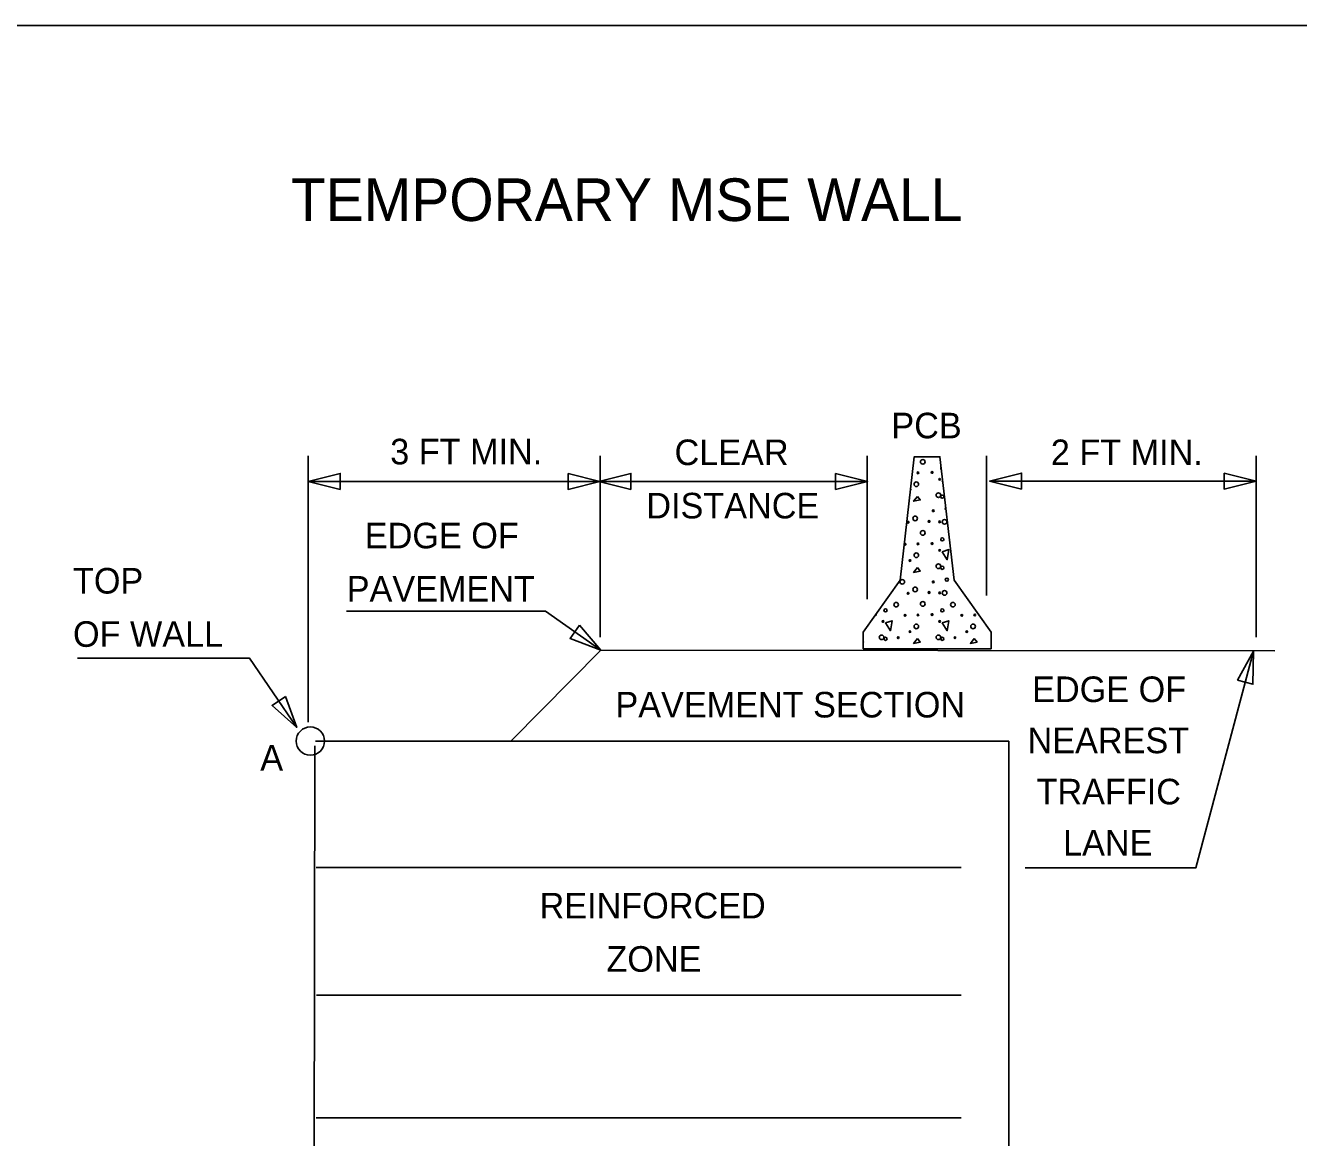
# Model space of a CAD drawing. Extents: x 2487012 to 2497594, y 369516 to 371986.
# Drawn here: x 2487358.3 to 2487671.9, y 370984.4 to 371258.3 of the extents above; entities that cross this region are included whole.
import ezdxf

# ---------------------------------------------------------------- set-up
doc = ezdxf.new("R2010")
doc.units = 0
for name, color, linetype in [('TC LABEL TEMP SHORING', 7, 'Continuous'), ('TC LABEL TEXT', 7, 'Continuous'), ('TC SHEET LAYOUT SHAPE', 7, 'Continuous')]:
    doc.layers.add(name, color=color, linetype=linetype)

msp = doc.modelspace()

# ---------------------------------------------------------------- linework, layer by layer
at = {"layer": 'TC LABEL TEMP SHORING'}
for p, q in [((2487427.93, 371086.68), (2487427.93, 371152.28)), ((2487499.91, 371107.65), (2487499.91, 371152.28)), ((2487565.64, 371117), (2487565.64, 371152.28)), ((2487595.06, 371117.94), (2487595.06, 371152.28)), ((2487661.45, 371107.65), (2487661.45, 371152.28)), ((2487584.22, 371146.19), (2487584.11, 371146.15)), ((2487584.11, 371146.15), (2487584.25, 371145.92)), ((2487600.51, 371082), (2487429.77, 371082)), ((2487600.51, 370878.76), (2487600.51, 371082)), ((2487429.59, 371080.9), (2487429.28, 370877.67)), ((2487429.94, 371050.89), (2487588.75, 371050.89)), ((2487429.98, 371019.52), (2487588.8, 371019.52)), ((2487429.94, 370989.28), (2487588.75, 370989.28))]:
    msp.add_line(p, q, dxfattribs=at)
for points in [[(2487564.64, 371104.8), (2487596.14, 371104.8), (2487596.14, 371108.85), (2487587.03, 371121.69), (2487583.55, 371152.05), (2487577.22, 371152.05), (2487573.74, 371121.69), (2487564.64, 371108.85)], [(2487578.01, 371142.31), (2487577.08, 371141.1), (2487578.72, 371141.42)], [(2487584.11, 371128.65), (2487585.35, 371126.72), (2487585.74, 371129.2)], [(2487578.01, 371124.81), (2487577.08, 371123.6), (2487578.72, 371123.92)], [(2487570.13, 371111.15), (2487571.37, 371109.22), (2487571.75, 371111.7)], [(2487584.11, 371111.15), (2487585.35, 371109.22), (2487585.74, 371111.7)], [(2487578.01, 371107.32), (2487577.08, 371106.1), (2487578.72, 371106.42)], [(2487591.99, 371107.32), (2487591.06, 371106.1), (2487592.7, 371106.42)]]:
    msp.add_lwpolyline(points, close=True, dxfattribs=at)
for points in [[(2487564.64, 371106.4), (2487564.74, 371106.42), (2487564.64, 371106.55)], [(2487478.05, 371082.22), (2487500.05, 371104.41), (2487666.03, 371104.31)]]:
    msp.add_lwpolyline(points, dxfattribs=at)
for centre, radius in [((2487579.33, 371150.82), 0.57), ((2487578.16, 371148.11), 0.209), ((2487581.63, 371148.2), 0.209), ((2487577.74, 371145.3), 0.57), ((2487583.5, 371146.51), 0.209), ((2487583.17, 371142.6), 0.57), ((2487584.13, 371142.23), 0.386), ((2487581.91, 371138.76), 0.209), ((2487575.72, 371135.95), 0.209), ((2487577.45, 371136.88), 0.57), ((2487580.88, 371136.14), 0.209), ((2487583.5, 371136.04), 0.209), ((2487584.69, 371136.04), 0.57), ((2487579.33, 371133.32), 0.57), ((2487584.13, 371131.73), 0.386), ((2487574.97, 371130.51), 0.209), ((2487577.74, 371127.8), 0.57), ((2487578.16, 371130.61), 0.209), ((2487581.63, 371130.7), 0.209), ((2487583.5, 371129.01), 0.209), ((2487576.19, 371126.51), 0.209), ((2487583.17, 371125.1), 0.57), ((2487584.13, 371124.73), 0.386), ((2487585.25, 371121.82), 0.386), ((2487574.27, 371121.26), 0.57), ((2487577.45, 371119.39), 0.57), ((2487580.88, 371118.64), 0.209), ((2487581.91, 371121.26), 0.209), ((2487583.5, 371118.54), 0.209), ((2487584.69, 371118.54), 0.57), ((2487572.77, 371115.64), 0.57), ((2487575.72, 371118.45), 0.209), ((2487579.33, 371115.82), 0.57), ((2487586.75, 371115.64), 0.57), ((2487570.15, 371114.23), 0.386), ((2487574.97, 371113.01), 0.209), ((2487578.16, 371113.11), 0.209), ((2487581.63, 371113.2), 0.209), ((2487584.13, 371114.23), 0.386), ((2487588.95, 371113.01), 0.209), ((2487592.14, 371113.11), 0.209), ((2487569.52, 371111.52), 0.209), ((2487577.74, 371110.3), 0.57), ((2487583.5, 371111.52), 0.209), ((2487591.72, 371110.3), 0.57), ((2487569.19, 371107.6), 0.57), ((2487570.15, 371107.23), 0.386), ((2487573.29, 371107.51), 0.209), ((2487576.19, 371109.01), 0.209), ((2487583.17, 371107.6), 0.57), ((2487584.13, 371107.23), 0.386), ((2487587.27, 371107.51), 0.209), ((2487590.17, 371109.01), 0.209)]:
    msp.add_circle(centre, radius, dxfattribs=at)
for centre, radius, start, end in [((2487584.13, 371149.23), 0.386, 137.1025, 235.9904), ((2487576.19, 371144.01), 0.209, 294.7417, 52.1654), ((2487585.25, 371139.32), 0.386, 134.7035, 238.3894), ((2487567.64, 371113.2), 0.209, 251.456, 37.8657)]:
    msp.add_arc(centre, radius, start, end, dxfattribs=at)
at = {"layer": 'TC LABEL TEXT'}
msp.add_line((2487595.79, 371146.09), (2487661.42, 371146.09), dxfattribs=at)
for points in [[(2487435.86, 371144.03), (2487427.98, 371146), (2487435.86, 371147.97)], [(2487435.86, 371144.03), (2487427.98, 371146), (2487435.86, 371147.97)], [(2487435.86, 371144.03), (2487427.98, 371146), (2487435.86, 371147.97)], [(2487435.86, 371144.03), (2487427.98, 371146), (2487435.86, 371147.97)], [(2487491.95, 371147.97), (2487499.83, 371146), (2487491.95, 371144.03)], [(2487491.95, 371147.97), (2487499.83, 371146), (2487491.95, 371144.03)], [(2487507.43, 371144.03), (2487499.55, 371146), (2487507.43, 371147.97)], [(2487507.43, 371144.03), (2487499.55, 371146), (2487507.43, 371147.97)], [(2487557.85, 371147.97), (2487565.73, 371146), (2487557.85, 371144.03)], [(2487557.85, 371147.97), (2487565.73, 371146), (2487557.85, 371144.03)], [(2487603.66, 371144.12), (2487595.79, 371146.09), (2487603.66, 371148.06)], [(2487603.66, 371144.12), (2487595.79, 371146.09), (2487603.66, 371148.06)], [(2487603.66, 371144.12), (2487595.79, 371146.09), (2487603.66, 371148.06)], [(2487603.66, 371144.12), (2487595.79, 371146.09), (2487603.66, 371148.06)], [(2487653.55, 371148.06), (2487661.42, 371146.09), (2487653.55, 371144.12)], [(2487653.55, 371148.06), (2487661.42, 371146.09), (2487653.55, 371144.12)], [(2487653.55, 371148.06), (2487661.42, 371146.09), (2487653.55, 371144.12)], [(2487653.55, 371148.06), (2487661.42, 371146.09), (2487653.55, 371144.12)], [(2487494.76, 371110.56), (2487500.05, 371104.41), (2487492.48, 371107.35)], [(2487494.76, 371110.56), (2487500.05, 371104.41), (2487492.48, 371107.35)], [(2487494.76, 371110.56), (2487500.05, 371104.41), (2487492.48, 371107.35)], [(2487494.76, 371110.56), (2487500.05, 371104.41), (2487492.48, 371107.35)], [(2487656.83, 371097.05), (2487660.75, 371104.16), (2487660.63, 371096.04)], [(2487656.83, 371097.05), (2487660.75, 371104.16), (2487660.63, 371096.04)], [(2487656.83, 371097.05), (2487660.75, 371104.16), (2487660.63, 371096.04)], [(2487656.83, 371097.05), (2487660.75, 371104.16), (2487660.63, 371096.04)], [(2487422.33, 371093.04), (2487425.14, 371085.43), (2487419.07, 371090.82)], [(2487422.33, 371093.04), (2487425.14, 371085.43), (2487419.07, 371090.82)], [(2487422.33, 371093.04), (2487425.14, 371085.43), (2487419.07, 371090.82)], [(2487422.33, 371093.04), (2487425.14, 371085.43), (2487419.07, 371090.82)]]:
    msp.add_lwpolyline(points, close=True, dxfattribs=at)
for points in [[(2487427.98, 371146), (2487499.55, 371146), (2487565.73, 371146)], [(2487437.37, 371114.08), (2487486.37, 371114.08), (2487500.05, 371104.41)], [(2487604.58, 371050.86), (2487646.61, 371050.86), (2487660.75, 371104.16)], [(2487371.13, 371102.43), (2487413.52, 371102.43), (2487425.14, 371085.43)]]:
    msp.add_lwpolyline(points, dxfattribs=at)
msp.add_circle((2487428.49, 371082.06), 3.48, dxfattribs=at)
at = {"layer": 'TC SHEET LAYOUT SHAPE'}
msp.add_lwpolyline([(2487016.56, 370666.84), (2487016.56, 370976.16), (2487016.56, 371248.27), (2487026.56, 371258.27), (2487469.58, 371258.27), (2487940.56, 371258.27), (2488261.56, 371258.27), (2488261.56, 371178.27), (2488346.56, 371178.27), (2488346.56, 371226.27), (2488506.56, 371226.27), (2488506.56, 370891.3), (2488506.56, 370612.1), (2488506.56, 370360.77), (2488151.56, 370360.77), (2488151.56, 370218.27), (2487778.38, 370218.27), (2487608.92, 370218.27), (2487256.14, 370218.27), (2487016.56, 370218.27)], close=True, dxfattribs=at)

# ---------------------------------------------------------------- texts
at = {"layer": 'TC LABEL TEXT'}
for s, height, p in [('TEMPORARY MSE WALL', 10.5, (2487423.71, 371210.12)), ('PCB', 6.3, (2487571.59, 371156.61)), ('3 FT MIN.', 6.3, (2487448.16, 371150.19)), ('CLEAR', 6.3, (2487518.19, 371150.01)), ('2 FT MIN.', 6.3, (2487610.87, 371150.01)), ('DISTANCE', 6.3, (2487511.24, 371136.88)), ('EDGE OF', 6.3, (2487441.91, 371129.52)), ('TOP ', 6.3, (2487370.03, 371118.38)), ('PAVEMENT', 6.3, (2487437.45, 371116.39)), ('OF WALL', 6.3, (2487370.03, 371105.26)), ('EDGE OF', 6.3, (2487606.27, 371091.66)), ('PAVEMENT SECTION', 6.3, (2487503.63, 371087.86)), ('NEAREST', 6.3, (2487605.14, 371079.06)), ('A', 6.3, (2487416.16, 371074.8)), ('TRAFFIC ', 6.3, (2487607.35, 371066.46)), ('LANE', 6.3, (2487613.88, 371053.86)), ('REINFORCED ', 6.3, (2487484.95, 371038.38)), ('ZONE', 6.3, (2487501.42, 371025.25))]:
    msp.add_text(s, height=height, dxfattribs=at).set_placement(p)

doc.saveas('drawing.dxf')
